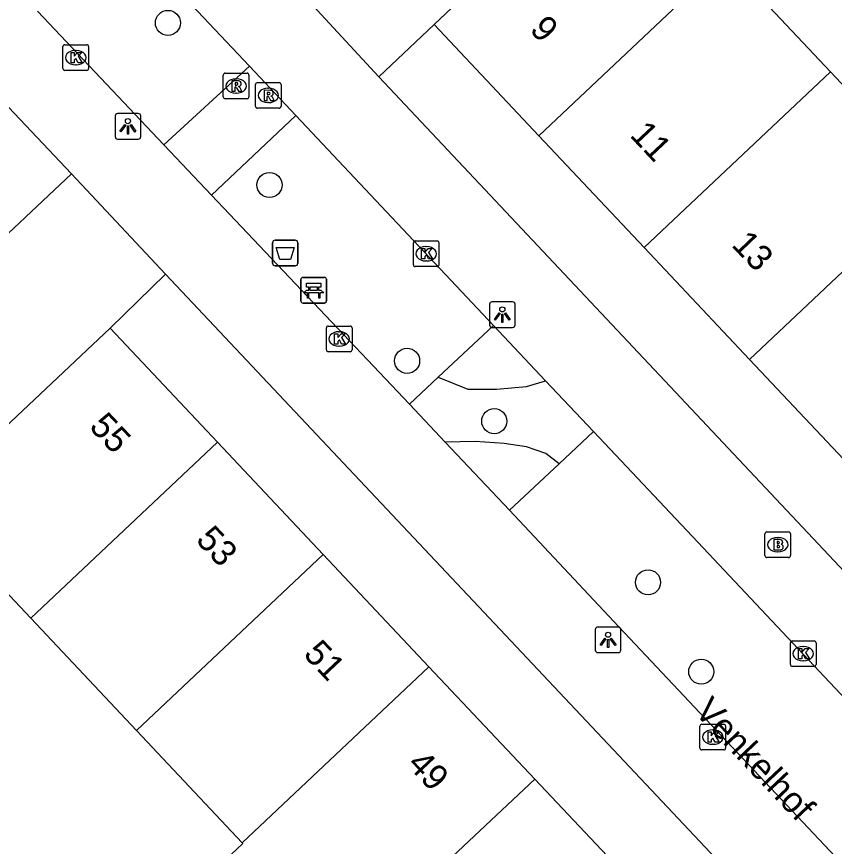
# Model space of a CAD drawing. Extents: x 162542 to 163144, y 380786 to 381511.
# Drawn here: x 162891.89 to 162923.82, y 381225.53 to 381257.93 of the extents above; entities that cross this region are included whole.
import ezdxf

# ---------------------------------------------------------------- set-up
doc = ezdxf.new("R2010")
doc.units = 0
for name, color, linetype in [('IMGEO_Afvalbak', 7, 'Continuous'), ('IMGEO_Bank', 7, 'Continuous'), ('IMGEO_Boom', 7, 'Continuous'), ('IMGEO_Brandkraan', 7, 'Continuous'), ('IMGEO_Groenvoorziening', 7, 'Continuous'), ('IMGEO_Kolk', 7, 'Continuous'), ('IMGEO_Lichtpunt', 7, 'Continuous'), ('IMGEO_Openbare_ruimte_label', 7, 'Continuous'), ('IMGEO_Pand', 7, 'Continuous'), ('IMGEO_Pand_nummerreeks', 7, 'Continuous'), ('IMGEO_Rijbaan_lokaal_open', 7, 'Continuous'), ('IMGEO_Rioolput', 7, 'Continuous'), ('IMGEO_Voetpad_open', 7, 'Continuous')]:
    doc.layers.add(name, color=color, linetype=linetype)

msp = doc.modelspace()

# ---------------------------------------------------------------- linework, layer by layer
at = {"layer": 'IMGEO_Afvalbak'}
for p, q in [((162901.879, 381248.297), (162901.879, 381249.097)), ((162901.879, 381249.097), (162901.879, 381248.297)), ((162901.979, 381249.197), (162902.769, 381249.197)), ((162902.769, 381249.197), (162901.979, 381249.197)), ((162902.869, 381249.097), (162902.869, 381248.297)), ((162902.869, 381248.297), (162902.869, 381249.097)), ((162902.769, 381248.197), (162901.979, 381248.197)), ((162901.979, 381248.197), (162902.769, 381248.197))]:
    msp.add_line(p, q, dxfattribs=at)
msp.add_lwpolyline([(162902.022, 381248.911), (162902.726, 381248.911), (162902.577, 381248.441), (162902.171, 381248.441), (162902.022, 381248.911)], dxfattribs=at)
for centre, start, end in [((162901.979, 381249.097), 90, 180), ((162901.979, 381249.097), 90, 180), ((162902.769, 381249.097), 0, 90), ((162902.769, 381249.097), 360, 90), ((162901.979, 381248.297), 180, 270), ((162901.979, 381248.297), 180, 270), ((162902.769, 381248.297), 270, 0), ((162902.769, 381248.297), 270, 0)]:
    msp.add_arc(centre, 0.1, start, end, dxfattribs=at)
at = {"layer": 'IMGEO_Bank'}
for p, q in [((162902.986, 381246.82), (162902.986, 381247.661)), ((162902.986, 381247.661), (162902.986, 381246.82)), ((162903.061, 381247.745), (162903.902, 381247.745)), ((162903.902, 381247.745), (162903.061, 381247.745)), ((162903.986, 381247.67), (162903.986, 381246.829)), ((162903.986, 381246.829), (162903.986, 381247.67)), ((162903.295, 381247.251), (162903.295, 381247.357)), ((162903.339, 381247.357), (162903.339, 381247.251)), ((162903.627, 381247.363), (162903.345, 381247.363)), ((162903.633, 381247.251), (162903.633, 381247.357)), ((162903.677, 381247.357), (162903.677, 381247.251)), ((162903.683, 381247.143), (162903.29, 381247.143)), ((162903.345, 381247.245), (162903.627, 381247.245)), ((162903.911, 381246.745), (162903.07, 381246.745)), ((162903.07, 381246.745), (162903.911, 381246.745))]:
    msp.add_line(p, q, dxfattribs=at)
for points in [[(162903.289, 381247.363), (162903.203, 381247.363), (162903.203, 381247.524), (162903.766, 381247.524), (162903.766, 381247.363), (162903.683, 381247.363)], [(162903.233, 381247.143), (162903.091, 381247.143), (162903.203, 381247.245), (162903.289, 381247.245)], [(162903.283, 381247.136), (162903.283, 381246.929), (162903.24, 381246.929), (162903.24, 381247.136)], [(162903.683, 381247.245), (162903.766, 381247.245), (162903.878, 381247.143), (162903.739, 381247.143)], [(162903.733, 381247.136), (162903.733, 381246.929), (162903.689, 381246.929), (162903.689, 381247.136)]]:
    msp.add_lwpolyline(points, dxfattribs=at)
for centre, radius, start, end in [((162903.064, 381247.667), 0.0779, 92.4484, 184.2845), ((162903.064, 381247.667), 0.0779, 92.4484, 184.2845), ((162903.908, 381247.667), 0.0779, 2.4484, 94.2845), ((162903.908, 381247.667), 0.0779, 2.4484, 94.2845), ((162903.288, 381247.356), 0.00671, 2.8957, 87.1043), ((162903.345, 381247.356), 0.00671, 92.8957, 177.1043), ((162903.627, 381247.356), 0.00671, 2.8957, 87.1043), ((162903.684, 381247.356), 0.00671, 92.8957, 177.1043), ((162903.233, 381247.136), 0.00671, 2.8957, 87.1043), ((162903.29, 381247.136), 0.00671, 92.8957, 177.1043), ((162903.288, 381247.252), 0.00671, 272.8957, 357.1043), ((162903.345, 381247.252), 0.00671, 182.8957, 267.1043), ((162903.627, 381247.252), 0.00671, 272.8957, 357.1043), ((162903.684, 381247.252), 0.00671, 182.8957, 267.1043), ((162903.682, 381247.136), 0.00671, 2.8957, 87.1043), ((162903.739, 381247.136), 0.00671, 92.8957, 177.1043), ((162903.064, 381246.823), 0.0779, 182.4484, 274.2845), ((162903.064, 381246.823), 0.0779, 182.4484, 274.2845), ((162903.908, 381246.823), 0.0779, 272.4484, 4.2845), ((162903.908, 381246.823), 0.0779, 272.4484, 4.2845)]:
    msp.add_arc(centre, radius, start, end, dxfattribs=at)
at = {"layer": 'IMGEO_Boom'}
for centre in [(162897.793, 381257.682), (162901.762, 381251.354), (162907.136, 381244.487), (162910.537, 381242.132), (162916.542, 381235.84), (162918.62, 381232.351)]:
    msp.add_circle(centre, 0.489, dxfattribs=at)
at = {"layer": 'IMGEO_Brandkraan'}
for p, q in [((162921.107, 381236.884), (162921.107, 381237.736)), ((162921.182, 381237.81), (162922.034, 381237.81)), ((162922.108, 381237.736), (162922.108, 381236.884)), ((162921.595, 381237.59), (162921.62, 381237.59)), ((162921.618, 381237.03), (162921.593, 381237.03)), ((162922.034, 381236.81), (162921.182, 381236.81))]:
    msp.add_line(p, q, dxfattribs=at)
for points in [[(162921.107, 381236.884), (162921.107, 381237.736)], [(162921.182, 381237.81), (162922.034, 381237.81)], [(162922.108, 381237.736), (162922.108, 381236.884)], [(162921.455, 381237.51), (162921.455, 381237.11), (162921.668, 381237.11)], [(162921.686, 381237.51), (162921.455, 381237.51)], [(162921.634, 381237.429), (162921.58, 381237.429), (162921.58, 381237.353)], [(162921.58, 381237.353), (162921.633, 381237.353)], [(162921.642, 381237.277), (162921.58, 381237.277), (162921.58, 381237.196)], [(162921.58, 381237.196), (162921.642, 381237.196)], [(162922.034, 381236.81), (162921.182, 381236.81)]]:
    msp.add_lwpolyline(points, dxfattribs=at)
for centre, radius, start, end in [((162921.184, 381237.734), 0.0765, 91.552, 178.448), ((162921.184, 381237.734), 0.0765, 91.552, 178.448), ((162922.032, 381237.734), 0.0765, 1.552, 88.448), ((162922.032, 381237.734), 0.0765, 1.552, 88.448), ((162921.635, 381237.391), 0.0379, 267.8285, 90.9355), ((162921.643, 381237.236), 0.0404, 269.8759, 90.5077), ((162921.69, 381237.365), 0.145, 59.4692, 91.5367), ((162921.715, 381237.412), 0.0922, 285.5137, 58.1501), ((162921.72, 381237.22), 0.105, 301.3115, 78.989), ((162921.674, 381237.361), 0.251, 268.6676, 293.5347), ((162921.184, 381236.886), 0.0765, 181.552, 268.448), ((162921.184, 381236.886), 0.0765, 181.552, 268.448), ((162922.032, 381236.886), 0.0765, 271.552, 358.448), ((162922.032, 381236.886), 0.0765, 271.552, 358.448)]:
    msp.add_arc(centre, radius, start, end, dxfattribs=at)
for centre, major_axis, ratio, start_param, end_param in [((162921.594, 381237.31), (-0.387, 0.002), 0.722429, 4.712389, 7.853982), ((162921.619, 381237.31), (-0.39, 0.002), 0.717154, 1.570796, 4.712389)]:
    msp.add_ellipse(centre, major_axis=major_axis, ratio=ratio, start_param=start_param, end_param=end_param, dxfattribs=at)
at = {"layer": 'IMGEO_Groenvoorziening'}
for points in [[(162908.346, 381243.846), (162909.507, 381243.379), (162910.623, 381243.379), (162911.795, 381243.491), (162912.542, 381243.713)], [(162913.071, 381240.471), (162912.558, 381240.867), (162911.795, 381241.128), (162910.921, 381241.258), (162909.786, 381241.332), (162908.622, 381241.317)]]:
    msp.add_lwpolyline(points, dxfattribs=at)
at = {"layer": 'IMGEO_Kolk'}
for p, q in [((162893.695, 381255.901), (162893.695, 381256.753)), ((162893.77, 381256.827), (162894.622, 381256.827)), ((162894.696, 381256.753), (162894.696, 381255.901)), ((162894.183, 381256.607), (162894.208, 381256.607)), ((162894.622, 381255.827), (162893.77, 381255.827)), ((162894.206, 381256.047), (162894.181, 381256.047)), ((162907.379, 381248.241), (162907.379, 381249.093)), ((162907.454, 381249.167), (162908.306, 381249.167)), ((162907.867, 381248.947), (162907.892, 381248.947)), ((162908.38, 381249.093), (162908.38, 381248.241)), ((162907.89, 381248.387), (162907.865, 381248.387)), ((162908.306, 381248.167), (162907.454, 381248.167)), ((162903.983, 381244.918), (162903.983, 381245.77)), ((162904.058, 381245.844), (162904.91, 381245.844)), ((162904.984, 381245.77), (162904.984, 381244.918)), ((162904.471, 381245.624), (162904.496, 381245.624)), ((162904.494, 381245.064), (162904.469, 381245.064)), ((162904.91, 381244.844), (162904.058, 381244.844)), ((162922.101, 381232.629), (162922.101, 381233.481)), ((162922.176, 381233.555), (162923.028, 381233.555)), ((162923.102, 381233.481), (162923.102, 381232.629)), ((162922.589, 381233.335), (162922.614, 381233.335)), ((162922.612, 381232.775), (162922.587, 381232.775)), ((162923.028, 381232.555), (162922.176, 381232.555)), ((162918.57, 381229.371), (162918.57, 381230.223)), ((162918.645, 381230.297), (162919.497, 381230.297)), ((162919.571, 381230.223), (162919.571, 381229.371)), ((162919.058, 381230.077), (162919.083, 381230.077)), ((162919.081, 381229.517), (162919.056, 381229.517)), ((162919.497, 381229.297), (162918.645, 381229.297))]:
    msp.add_line(p, q, dxfattribs=at)
for points in [[(162893.695, 381255.901), (162893.695, 381256.753)], [(162893.77, 381256.827), (162894.622, 381256.827)], [(162894.696, 381256.753), (162894.696, 381255.901)], [(162894.016, 381256.527), (162894.139, 381256.527), (162894.139, 381256.376), (162894.269, 381256.527), (162894.433, 381256.527), (162894.287, 381256.376), (162894.44, 381256.127), (162894.288, 381256.127), (162894.203, 381256.291), (162894.139, 381256.224), (162894.139, 381256.127), (162894.016, 381256.127), (162894.016, 381256.527)], [(162894.622, 381255.827), (162893.77, 381255.827)], [(162907.379, 381248.241), (162907.379, 381249.093)], [(162907.454, 381249.167), (162908.306, 381249.167)], [(162908.38, 381249.093), (162908.38, 381248.241)], [(162907.7, 381248.867), (162907.823, 381248.867), (162907.823, 381248.716), (162907.953, 381248.867), (162908.117, 381248.867), (162907.971, 381248.716), (162908.124, 381248.467), (162907.972, 381248.467), (162907.887, 381248.631), (162907.823, 381248.564), (162907.823, 381248.467), (162907.7, 381248.467), (162907.7, 381248.867)], [(162908.306, 381248.167), (162907.454, 381248.167)], [(162903.983, 381244.918), (162903.983, 381245.77)], [(162904.058, 381245.844), (162904.91, 381245.844)], [(162904.984, 381245.77), (162904.984, 381244.918)], [(162904.304, 381245.544), (162904.427, 381245.544), (162904.427, 381245.393), (162904.557, 381245.544), (162904.721, 381245.544), (162904.575, 381245.393), (162904.728, 381245.144), (162904.576, 381245.144), (162904.491, 381245.308), (162904.427, 381245.241), (162904.427, 381245.144), (162904.304, 381245.144), (162904.304, 381245.544)], [(162904.91, 381244.844), (162904.058, 381244.844)], [(162922.101, 381232.629), (162922.101, 381233.481)], [(162922.176, 381233.555), (162923.028, 381233.555)], [(162923.102, 381233.481), (162923.102, 381232.629)], [(162922.422, 381233.255), (162922.545, 381233.255), (162922.545, 381233.104), (162922.675, 381233.255), (162922.839, 381233.255), (162922.693, 381233.104), (162922.846, 381232.855), (162922.694, 381232.855), (162922.609, 381233.019), (162922.545, 381232.952), (162922.545, 381232.855), (162922.422, 381232.855), (162922.422, 381233.255)], [(162923.028, 381232.555), (162922.176, 381232.555)], [(162918.57, 381229.371), (162918.57, 381230.223)], [(162918.645, 381230.297), (162919.497, 381230.297)], [(162919.571, 381230.223), (162919.571, 381229.371)], [(162918.891, 381229.997), (162919.014, 381229.997), (162919.014, 381229.846), (162919.144, 381229.997), (162919.308, 381229.997), (162919.162, 381229.846), (162919.315, 381229.597), (162919.163, 381229.597), (162919.078, 381229.761), (162919.014, 381229.694), (162919.014, 381229.597), (162918.891, 381229.597), (162918.891, 381229.997)], [(162919.497, 381229.297), (162918.645, 381229.297)]]:
    msp.add_lwpolyline(points, dxfattribs=at)
for centre, start, end in [((162893.772, 381256.751), 91.552, 178.448), ((162893.772, 381256.751), 91.552, 178.448), ((162894.62, 381256.751), 1.552, 88.448), ((162894.62, 381256.751), 1.552, 88.448), ((162893.772, 381255.903), 181.552, 268.448), ((162893.772, 381255.903), 181.552, 268.448), ((162894.62, 381255.903), 271.552, 358.448), ((162894.62, 381255.903), 271.552, 358.448), ((162907.456, 381249.091), 91.552, 178.448), ((162907.456, 381249.091), 91.552, 178.448), ((162908.304, 381249.091), 1.552, 88.448), ((162908.304, 381249.091), 1.552, 88.448), ((162907.456, 381248.243), 181.552, 268.448), ((162907.456, 381248.243), 181.552, 268.448), ((162908.304, 381248.243), 271.552, 358.448), ((162908.304, 381248.243), 271.552, 358.448), ((162904.06, 381245.768), 91.552, 178.448), ((162904.06, 381245.768), 91.552, 178.448), ((162904.908, 381245.768), 1.552, 88.448), ((162904.908, 381245.768), 1.552, 88.448), ((162904.06, 381244.92), 181.552, 268.448), ((162904.06, 381244.92), 181.552, 268.448), ((162904.908, 381244.92), 271.552, 358.448), ((162904.908, 381244.92), 271.552, 358.448), ((162922.178, 381233.479), 91.552, 178.448), ((162922.178, 381233.479), 91.552, 178.448), ((162923.026, 381233.479), 1.552, 88.448), ((162923.026, 381233.479), 1.552, 88.448), ((162922.178, 381232.631), 181.552, 268.448), ((162922.178, 381232.631), 181.552, 268.448), ((162923.026, 381232.631), 271.552, 358.448), ((162923.026, 381232.631), 271.552, 358.448), ((162918.647, 381230.221), 91.552, 178.448), ((162918.647, 381230.221), 91.552, 178.448), ((162919.495, 381230.221), 1.552, 88.448), ((162919.495, 381230.221), 1.552, 88.448), ((162918.647, 381229.373), 181.552, 268.448), ((162918.647, 381229.373), 181.552, 268.448), ((162919.495, 381229.373), 271.552, 358.448), ((162919.495, 381229.373), 271.552, 358.448)]:
    msp.add_arc(centre, 0.0765, start, end, dxfattribs=at)
for centre, major_axis, ratio, start_param, end_param in [((162894.182, 381256.327), (-0.387, 0.002), 0.722429, 4.712389, 7.853982), ((162894.207, 381256.327), (-0.39, 0.002), 0.717154, 1.570796, 4.712389), ((162907.866, 381248.667), (-0.387, 0.002), 0.722429, 4.712389, 7.853982), ((162907.891, 381248.667), (-0.39, 0.002), 0.717154, 1.570796, 4.712389), ((162904.47, 381245.344), (-0.387, 0.002), 0.722429, 4.712389, 7.853982), ((162904.495, 381245.344), (-0.39, 0.002), 0.717154, 1.570796, 4.712389), ((162922.588, 381233.055), (-0.387, 0.002), 0.722429, 4.712389, 7.853982), ((162922.613, 381233.055), (-0.39, 0.002), 0.717154, 1.570796, 4.712389), ((162919.057, 381229.797), (-0.387, 0.002), 0.722429, 4.712389, 7.853982), ((162919.082, 381229.797), (-0.39, 0.002), 0.717154, 1.570796, 4.712389)]:
    msp.add_ellipse(centre, major_axis=major_axis, ratio=ratio, start_param=start_param, end_param=end_param, dxfattribs=at)
at = {"layer": 'IMGEO_Lichtpunt'}
for p, q in [((162896.638, 381254.143), (162895.83, 381254.143)), ((162896.638, 381254.143), (162895.83, 381254.143)), ((162895.736, 381254.048), (162895.736, 381253.241)), ((162895.736, 381254.048), (162895.736, 381253.241)), ((162896.732, 381253.241), (162896.732, 381254.048)), ((162896.732, 381253.241), (162896.732, 381254.048)), ((162895.83, 381253.147), (162896.638, 381253.147)), ((162895.83, 381253.147), (162896.638, 381253.147)), ((162910.354, 381246.696), (162910.354, 381245.889)), ((162910.354, 381246.696), (162910.354, 381245.889)), ((162911.256, 381246.791), (162910.448, 381246.791)), ((162911.256, 381246.791), (162910.448, 381246.791)), ((162911.35, 381245.889), (162911.35, 381246.696)), ((162911.35, 381245.889), (162911.35, 381246.696)), ((162910.448, 381245.795), (162911.256, 381245.795)), ((162910.448, 381245.795), (162911.256, 381245.795)), ((162915.386, 381234.092), (162914.578, 381234.092)), ((162915.386, 381234.092), (162914.578, 381234.092)), ((162914.484, 381233.997), (162914.484, 381233.19)), ((162914.484, 381233.997), (162914.484, 381233.19)), ((162915.48, 381233.19), (162915.48, 381233.997)), ((162915.48, 381233.19), (162915.48, 381233.997)), ((162914.578, 381233.096), (162915.386, 381233.096)), ((162914.578, 381233.096), (162915.386, 381233.096))]:
    msp.add_line(p, q, dxfattribs=at)
for points in [[(162896.11, 381253.712), (162896.149, 381253.684), (162895.961, 381253.422), (162895.923, 381253.449), (162896.11, 381253.712)], [(162896.212, 381253.664), (162896.259, 381253.664), (162896.259, 381253.342), (162896.212, 381253.342), (162896.212, 381253.664)], [(162896.322, 381253.684), (162896.36, 381253.711), (162896.547, 381253.449), (162896.508, 381253.421), (162896.322, 381253.684)], [(162910.728, 381246.36), (162910.767, 381246.332), (162910.579, 381246.07), (162910.541, 381246.097), (162910.728, 381246.36)], [(162910.94, 381246.332), (162910.978, 381246.359), (162911.165, 381246.097), (162911.126, 381246.069), (162910.94, 381246.332)], [(162910.83, 381246.312), (162910.877, 381246.312), (162910.877, 381245.99), (162910.83, 381245.99), (162910.83, 381246.312)], [(162914.858, 381233.661), (162914.897, 381233.633), (162914.709, 381233.371), (162914.671, 381233.398), (162914.858, 381233.661)], [(162914.96, 381233.613), (162915.007, 381233.613), (162915.007, 381233.291), (162914.96, 381233.291), (162914.96, 381233.613)], [(162915.07, 381233.633), (162915.108, 381233.66), (162915.295, 381233.398), (162915.256, 381233.37), (162915.07, 381233.633)]]:
    msp.add_lwpolyline(points, dxfattribs=at)
for centre in [(162896.235, 381253.846), (162910.853, 381246.494), (162914.983, 381233.795)]:
    msp.add_circle(centre, 0.0994, dxfattribs=at)
for centre, start, end in [((162895.83, 381254.048), 90, 180), ((162895.83, 381254.048), 90, 180), ((162896.638, 381254.048), 0, 90), ((162896.638, 381254.048), 0, 90), ((162895.83, 381253.241), 180, 270), ((162895.83, 381253.241), 180, 270), ((162896.638, 381253.241), 270, 0), ((162896.638, 381253.241), 270, 360), ((162910.448, 381246.696), 90, 180), ((162910.448, 381246.696), 90, 180), ((162911.256, 381246.696), 0, 90), ((162911.256, 381246.696), 0, 90), ((162910.448, 381245.889), 180, 270), ((162910.448, 381245.889), 180, 270), ((162911.256, 381245.889), 270, 0), ((162911.256, 381245.889), 270, 360), ((162914.578, 381233.997), 90, 180), ((162914.578, 381233.997), 90, 180), ((162915.386, 381233.997), 0, 90), ((162915.386, 381233.997), 0, 90), ((162914.578, 381233.19), 180, 270), ((162914.578, 381233.19), 180, 270), ((162915.386, 381233.19), 270, 0), ((162915.386, 381233.19), 270, 360)]:
    msp.add_arc(centre, 0.0946, start, end, dxfattribs=at)
at = {"layer": 'IMGEO_Pand'}
for points in [[(162908.191, 381257.623), (162915.467, 381264.485)], [(162919.558, 381260.139), (162912.283, 381253.278)], [(162923.671, 381255.771), (162919.558, 381260.139)], [(162908.191, 381257.623), (162912.283, 381253.278)], [(162916.396, 381248.91), (162923.671, 381255.771)], [(162927.784, 381251.402), (162923.671, 381255.771)], [(162912.283, 381253.278), (162916.396, 381248.91)], [(162927.784, 381251.402), (162920.51, 381244.542)], [(162920.51, 381244.542), (162916.396, 381248.91)], [(162888.236, 381238.896), (162895.536, 381245.762)], [(162895.536, 381245.762), (162899.733, 381241.306)], [(162920.51, 381244.542), (162924.623, 381240.174)], [(162899.733, 381241.306), (162892.44, 381234.436)], [(162903.861, 381236.925), (162899.733, 381241.306)], [(162892.44, 381234.436), (162888.236, 381238.896)], [(162896.568, 381230.055), (162903.861, 381236.925)], [(162903.861, 381236.925), (162907.989, 381232.543)], [(162896.568, 381230.055), (162892.44, 381234.436)], [(162907.989, 381232.543), (162900.697, 381225.673)], [(162912.117, 381228.161), (162907.989, 381232.543)], [(162900.697, 381225.673), (162896.568, 381230.055)], [(162904.939, 381221.172), (162904.826, 381221.292), (162912.117, 381228.161)], [(162916.245, 381223.779), (162912.117, 381228.161)], [(162904.939, 381221.172), (162901.967, 381218.373), (162897.754, 381222.845), (162900.725, 381225.644), (162900.697, 381225.673)]]:
    msp.add_lwpolyline(points, dxfattribs=at)
at = {"layer": 'IMGEO_Rijbaan_lokaal_open'}
for points in [[(162906.029, 381255.574), (162902.331, 381259.587)], [(162906.029, 381255.574), (162908.191, 381257.623)], [(162900.978, 381255.987), (162897.636, 381252.919)], [(162900.978, 381255.987), (162902.789, 381254.064)], [(162899.498, 381250.953), (162902.789, 381254.064)], [(162899.498, 381250.953), (162897.636, 381252.919)]]:
    msp.add_lwpolyline(points, dxfattribs=at)
at = {"layer": 'IMGEO_Rioolput'}
for p, q in [((162899.956, 381254.792), (162899.956, 381255.644)), ((162900.031, 381255.718), (162900.883, 381255.718)), ((162900.444, 381255.498), (162900.469, 381255.498)), ((162900.957, 381255.644), (162900.957, 381254.792)), ((162901.214, 381254.424), (162901.214, 381255.276)), ((162901.289, 381255.35), (162902.141, 381255.35)), ((162901.702, 381255.13), (162901.727, 381255.13)), ((162902.215, 381255.276), (162902.215, 381254.424)), ((162900.467, 381254.938), (162900.442, 381254.938)), ((162900.883, 381254.718), (162900.031, 381254.718)), ((162901.725, 381254.57), (162901.7, 381254.57)), ((162902.141, 381254.35), (162901.289, 381254.35))]:
    msp.add_line(p, q, dxfattribs=at)
for points in [[(162899.956, 381254.792), (162899.956, 381255.644)], [(162900.031, 381255.718), (162900.883, 381255.718)], [(162900.545, 381255.416), (162900.293, 381255.418), (162900.293, 381255.018)], [(162900.957, 381255.644), (162900.957, 381254.792)], [(162900.293, 381255.018), (162900.417, 381255.018), (162900.417, 381255.18), (162900.428, 381255.18)], [(162900.471, 381255.337), (162900.417, 381255.337), (162900.417, 381255.256)], [(162900.417, 381255.256), (162900.469, 381255.256)], [(162900.475, 381255.151), (162900.546, 381255.018), (162900.686, 381255.018), (162900.621, 381255.144)], [(162901.214, 381254.424), (162901.214, 381255.276)], [(162901.289, 381255.35), (162902.141, 381255.35)], [(162902.215, 381255.276), (162902.215, 381254.424)], [(162901.803, 381255.048), (162901.551, 381255.05), (162901.551, 381254.65)], [(162901.551, 381254.65), (162901.675, 381254.65), (162901.675, 381254.812), (162901.686, 381254.812)], [(162901.729, 381254.969), (162901.675, 381254.969), (162901.675, 381254.888)], [(162901.675, 381254.888), (162901.727, 381254.888)], [(162901.733, 381254.783), (162901.804, 381254.65), (162901.944, 381254.65), (162901.879, 381254.776)], [(162900.883, 381254.718), (162900.031, 381254.718)], [(162902.141, 381254.35), (162901.289, 381254.35)]]:
    msp.add_lwpolyline(points, dxfattribs=at)
for centre, radius, start, end in [((162900.033, 381255.642), 0.0765, 91.552, 178.448), ((162900.033, 381255.642), 0.0765, 91.552, 178.448), ((162900.881, 381255.642), 0.0765, 1.552, 88.448), ((162900.881, 381255.642), 0.0765, 1.552, 88.448), ((162900.427, 381255.127), 0.0533, 26.0293, 88.6989), ((162900.453, 381255.445), 0.19, 274.7715, 282.9687), ((162900.477, 381255.241), 0.0964, 77.0061, 93.1865), ((162900.491, 381255.298), 0.0378, 276.6634, 79.6772), ((162900.544, 381255.306), 0.109, 350.3612, 89.416), ((162900.542, 381255.306), 0.112, 277.5842, 350.9817), ((162900.526, 381255.091), 0.108, 29.5134, 73.7905), ((162901.291, 381255.274), 0.0765, 91.552, 178.448), ((162901.291, 381255.274), 0.0765, 91.552, 178.448), ((162902.139, 381255.274), 0.0765, 1.552, 88.448), ((162902.139, 381255.274), 0.0765, 1.552, 88.448), ((162900.033, 381254.794), 0.0765, 181.552, 268.448), ((162900.033, 381254.794), 0.0765, 181.552, 268.448), ((162900.881, 381254.794), 0.0765, 271.552, 358.448), ((162900.881, 381254.794), 0.0765, 271.552, 358.448), ((162901.685, 381254.759), 0.0533, 26.0293, 88.6989), ((162901.711, 381255.077), 0.19, 274.7715, 282.9687), ((162901.735, 381254.873), 0.0964, 77.0061, 93.1865), ((162901.749, 381254.93), 0.0378, 276.6634, 79.6772), ((162901.802, 381254.938), 0.109, 350.3612, 89.416), ((162901.8, 381254.938), 0.112, 277.5842, 350.9817), ((162901.784, 381254.723), 0.108, 29.5134, 73.7905), ((162901.291, 381254.426), 0.0765, 181.552, 268.448), ((162901.291, 381254.426), 0.0765, 181.552, 268.448), ((162902.139, 381254.426), 0.0765, 271.552, 358.448), ((162902.139, 381254.426), 0.0765, 271.552, 358.448)]:
    msp.add_arc(centre, radius, start, end, dxfattribs=at)
for centre, major_axis, ratio, start_param, end_param in [((162900.443, 381255.218), (-0.387, 0.002), 0.722429, 4.712389, 7.853982), ((162900.468, 381255.218), (-0.39, 0.002), 0.717154, 1.570796, 4.712389), ((162901.701, 381254.85), (-0.387, 0.002), 0.722429, 4.712389, 7.853982), ((162901.726, 381254.85), (-0.39, 0.002), 0.717154, 1.570796, 4.712389)]:
    msp.add_ellipse(centre, major_axis=major_axis, ratio=ratio, start_param=start_param, end_param=end_param, dxfattribs=at)
at = {"layer": 'IMGEO_Voetpad_open'}
for points in [[(162865.48, 381282.064), (162871.275, 381275.979), (162871.311, 381275.941), (162873.07, 381274.077), (162878.582, 381268.238), (162880.297, 381266.406), (162887.54, 381258.657), (162894.031, 381251.782)], [(162896.025, 381261.248), (162900.978, 381255.987)], [(162897.636, 381252.919), (162892.698, 381258.134)], [(162951.248, 381207.533), (162947.383, 381211.626), (162906.029, 381255.574)], [(162902.789, 381254.064), (162910.507, 381245.873)], [(162894.031, 381251.782), (162837.429, 381198.492), (162842.87, 381158.314)], [(162894.031, 381251.782), (162897.699, 381247.866)], [(162907.224, 381242.793), (162899.498, 381250.953)], [(162895.536, 381245.762), (162897.699, 381247.866)], [(162897.699, 381247.866), (162926.773, 381216.999), (162930.637, 381212.889)], [(162910.507, 381245.873), (162908.346, 381243.846)], [(162910.507, 381245.873), (162912.542, 381243.713)], [(162908.346, 381243.846), (162907.224, 381242.793)], [(162912.542, 381243.713), (162914.411, 381241.729)], [(162908.622, 381241.317), (162907.224, 381242.793)], [(162913.071, 381240.471), (162914.411, 381241.729)], [(162914.411, 381241.729), (162918.482, 381237.409), (162927.981, 381227.327)], [(162911.139, 381238.659), (162908.622, 381241.317)], [(162911.139, 381238.659), (162913.071, 381240.471)], [(162924.695, 381224.244), (162915.191, 381234.33), (162911.139, 381238.659)]]:
    msp.add_lwpolyline(points, dxfattribs=at)

# ---------------------------------------------------------------- texts
at = {"layer": 'IMGEO_Openbare_ruimte_label'}
msp.add_text('Venkelhof', height=1, rotation=313.3796, dxfattribs=at).set_placement((162918.313, 381230.766))
at = {"layer": 'IMGEO_Pand_nummerreeks'}
for s, rotation, p in [('9', 313.1283, (162911.883, 381257.389)), ('11', 313.1759, (162915.795, 381253.275)), ('13', 313.7106, (162919.768, 381248.987)), ('55', 313.2901, (162894.683, 381241.884)), ('53', 313.2901, (162898.845, 381237.466)), ('51', 313.2901, (162903.048, 381233.004)), ('49', 313.2925, (162907.099, 381228.705))]:
    msp.add_text(s, height=1, rotation=rotation, dxfattribs=at).set_placement(p)

doc.saveas('drawing.dxf')
